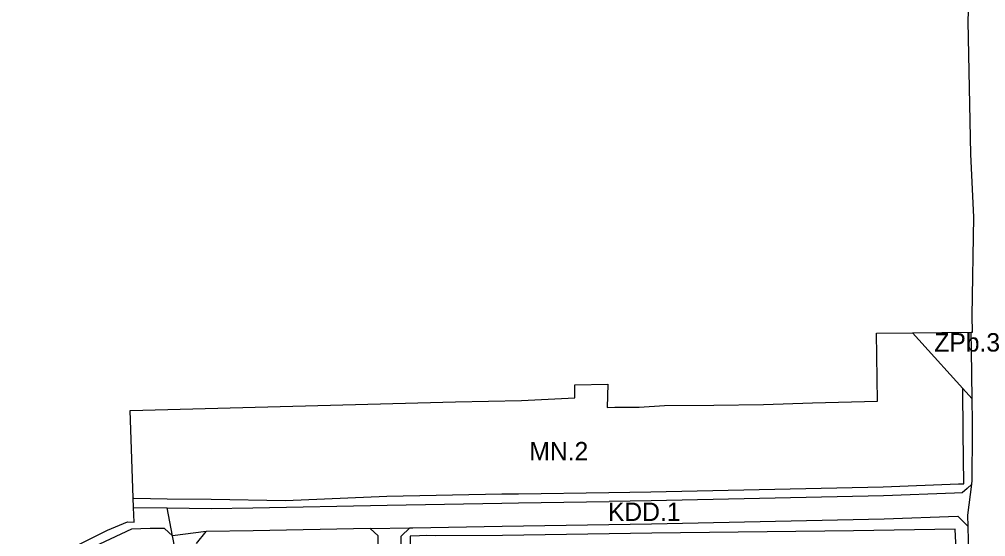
# Model space of a CAD drawing. Extents: x 7431080 to 7433370, y 5546450 to 5548428.
# Drawn here: x 7431233.8 to 7431653, y 5547286.3 to 5547510.7 of the extents above; entities that cross this region are included whole.
import ezdxf

# ---------------------------------------------------------------- set-up
doc = ezdxf.new("R2010")
doc.units = 0
for name, color, linetype in [('Linie Rozgraniczajace', 7, 'Continuous'), ('nieprzekraczalna linia zabudowy', 7, 'Continuous'), ('oznaczenia_przeznaczen', 7, 'Continuous')]:
    doc.layers.add(name, color=color, linetype=linetype)

msp = doc.modelspace()

# ---------------------------------------------------------------- linework, layer by layer
at = {"layer": 'Linie Rozgraniczajace'}
for points in [[(7431251.16, 5547278.75), (7431272.11, 5547289.12), (7431277.27, 5547291.27), (7431280.68, 5547292.71), (7431283.57, 5547292.69), (7431283.35, 5547298.97), (7431281.87, 5547340.99), (7431423.02, 5547344.75), (7431451.67, 5547345.43), (7431474.74, 5547346.47), (7431474.71, 5547352.17), (7431489.11, 5547352.46), (7431488.86, 5547342.3), (7431492.16, 5547342.5), (7431502.66, 5547342.5), (7431513.74, 5547343.19), (7431535.13, 5547343.38), (7431556.56, 5547343.69), (7431577.96, 5547344.36), (7431606.03, 5547345.11), (7431605.72, 5547374.59), (7431621.22, 5547374.72), (7431646.77, 5547374.95), (7431647.33, 5547374.95), (7431647.19, 5547382.14), (7431647.85, 5547424.93), (7431646.57, 5547452.17), (7431645.39, 5547509.8), (7431645.69, 5547518.66)], [(7431647.11, 5547346.06), (7431621.22, 5547374.72)], [(7431647.23, 5547331.45), (7431647.23, 5547336.04), (7431647.11, 5547346.06), (7431646.86, 5547367.14), (7431646.77, 5547374.95)], [(7431645.25, 5547295.66), (7431647, 5547309.09), (7431647.2, 5547310.64), (7431647.23, 5547331.45)], [(7431647, 5547309.09), (7431644.93, 5547307.18), (7431642.86, 5547305.28), (7431639.44, 5547305.15), (7431608.68, 5547304.01), (7431507.88, 5547301.83), (7431489.63, 5547301.56)], [(7431283.35, 5547298.97), (7431297.91, 5547298.79), (7431317.06, 5547298.62), (7431335.04, 5547298.86), (7431393.31, 5547299.96), (7431443.12, 5547300.86), (7431450.41, 5547300.97)], [(7431390.34, 5546954.83), (7431378.8, 5546959.84), (7431372.11, 5546985.69), (7431365.42, 5547011.53), (7431357.5, 5547039.75), (7431342.29, 5547057.75), (7431329.25, 5547071.13), (7431317.06, 5547095.73), (7431318.2, 5547101.16), (7431317.29, 5547113.99), (7431318.15, 5547129.1), (7431321.47, 5547149.42), (7431322.16, 5547159.21), (7431321.76, 5547169.51), (7431319.7, 5547184.04), (7431316.79, 5547198.96), (7431310.88, 5547230.65), (7431309.31, 5547238.54), (7431303.61, 5547269.63), (7431300.27, 5547286.7), (7431297.91, 5547298.79)], [(7431450.41, 5547300.97), (7431489.63, 5547301.56)], [(7431400.09, 5547208.92), (7431399.5, 5547284.55), (7431399.48, 5547285.56), (7431399.47, 5547286.56), (7431403.16, 5547290.15), (7431404.45, 5547290.17), (7431443.28, 5547290.86), (7431508.06, 5547291.84), (7431608.94, 5547294.01), (7431608.98, 5547294.02), (7431609.02, 5547294.01), (7431640.93, 5547295.19), (7431645.37, 5547290.69)], [(7431646.11, 5547229.52), (7431645.64, 5547251.49), (7431645.76, 5547273.63), (7431645.5, 5547284.65), (7431645.37, 5547290.69), (7431645.25, 5547295.66)], [(7431296.74, 5547289.94), (7431290.55, 5547289.81), (7431282.39, 5547289.64), (7431233.79, 5547266.7)], [(7431300.27, 5547286.7), (7431296.74, 5547289.94)], [(7431386.05, 5547289.82), (7431335.2, 5547288.86), (7431314.85, 5547288.59), (7431300.27, 5547286.7)], [(7431310.62, 5547283.33), (7431314.85, 5547288.59)], [(7431411.39, 5547106.3), (7431398.16, 5547152.21), (7431393.99, 5547166.85), (7431393.97, 5547167.03), (7431393.91, 5547167.2), (7431392.59, 5547173.5), (7431392.56, 5547173.72), (7431392.54, 5547173.81), (7431391.42, 5547181.59), (7431391.4, 5547181.85), (7431391.39, 5547181.88), (7431390.2, 5547196.73), (7431390.22, 5547196.91), (7431390.18, 5547197.1), (7431389.5, 5547286.74), (7431386.05, 5547289.82), (7431403.16, 5547290.15)]]:
    msp.add_lwpolyline(points, dxfattribs=at)
at = {"layer": 'nieprzekraczalna linia zabudowy'}
msp.add_line((7431450.35, 5547304.97), (7431489.57, 5547305.56), dxfattribs=at)
for points in [[(7431643.52, 5547309.27), (7431643.23, 5547331.45), (7431643.23, 5547336.02), (7431643.11, 5547346.03), (7431643.11, 5547346.04), (7431643.06, 5547350.55)], [(7431489.57, 5547305.56), (7431507.81, 5547305.83), (7431608.56, 5547308.01), (7431641.23, 5547309.22), (7431643.52, 5547309.27)], [(7431283.4, 5547302.97), (7431297.95, 5547302.79), (7431317.05, 5547302.62), (7431349.29, 5547302.03), (7431393.24, 5547303.96), (7431443.05, 5547304.86), (7431450.35, 5547304.97)], [(7431639.82, 5547289.54), (7431595.73, 5547288.84), (7431595.69, 5547288.85), (7431508.13, 5547287.84), (7431443.35, 5547286.86), (7431414.43, 5547286.74), (7431410.39, 5547286.82), (7431407.38, 5547286.63), (7431403.39, 5547286.61), (7431403.43, 5547277.15), (7431405.43, 5547218.72), (7431405.51, 5547207.73)], [(7431640.76, 5547213.56), (7431640.52, 5547229.97), (7431640.05, 5547251.99), (7431640.17, 5547280.75), (7431639.82, 5547289.54)]]:
    msp.add_lwpolyline(points, dxfattribs=at)

# ---------------------------------------------------------------- texts
at = {"layer": 'oznaczenia_przeznaczen'}
for s, p in [('ZPb.3', (7431630.73, 5547366.6)), ('ZPb.3', (7431630.73, 5547366.6)), ('MN.2', (7431455.04, 5547319.4)), ('MN.2', (7431455.04, 5547319.4)), ('KDD.1', (7431489.12, 5547293.13)), ('KDD.1', (7431489.12, 5547293.13))]:
    msp.add_text(s, height=8, dxfattribs=at).set_placement(p)

doc.saveas('drawing.dxf')
